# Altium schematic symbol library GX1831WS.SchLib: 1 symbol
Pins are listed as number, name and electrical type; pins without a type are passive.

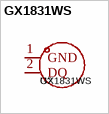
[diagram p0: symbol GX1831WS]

## GX1831WS
designator U?
footprint TO-92S-2_L4.0-W1.5-P1.27-L
pins: 1 GND, 2 DQ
